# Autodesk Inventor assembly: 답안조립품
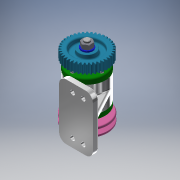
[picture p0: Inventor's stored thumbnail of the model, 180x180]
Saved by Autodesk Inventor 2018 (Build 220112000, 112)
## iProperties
Created: 2023-08
Part Number: 답안조립품
Material: 일반
Document SubType Name: Assembly
Designer: home
Author: home
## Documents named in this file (12)
- C:\Users\home\Desktop\730806V1009\답안조립품.iam
- C:\Users\home\Desktop\730806V1009\본체.ipt
- C:\Users\home\Desktop\730806V1009\베어링 6204.ipt
- C:\Users\home\Desktop\730806V1009\축.ipt
- C:\Users\home\Desktop\730806V1009\커버.ipt
- C:\Users\home\Desktop\730806V1009\오일실 20x35x8.ipt
- C:\Users\home\Desktop\730806V1009\볼트 M4 x 12.ipt
- C:\Users\home\Desktop\730806V1009\키 5x5.ipt
- C:\Users\home\Desktop\730806V1009\V벨트풀리.ipt
- C:\Users\home\Desktop\730806V1009\스퍼기어.ipt
- C:\Users\home\Desktop\730806V1009\와셔 12x24.ipt
- C:\Users\home\Desktop\730806V1009\너트 M12x1.25.ipt
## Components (1 placed, 1 different names)
1. V벨트풀리:1
